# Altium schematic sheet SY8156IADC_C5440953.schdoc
size 127 x 101 mm
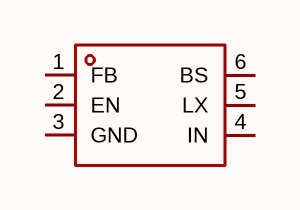
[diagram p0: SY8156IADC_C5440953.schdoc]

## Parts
U?  sy8156iadc_c5440953  [TSOT-23-6_L2.9-W1.6-P0.95-LS2.8-BL]  (value not drawn)

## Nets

Not connected (* = marked no-connect by the designer): U? 1(FB) 2(EN) 3(GND) 4(IN) 5(LX) 6(BS)

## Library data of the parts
U? = sy8156iadc_c5440953: 功能类型:降压型;工作电压:4.5V~18V;输出电压:3.3V;输出电流:6A;输出类型:固定;; Manufacturer: Silergy(矽力杰); AddInBom: yes; ModelId: 2c4039b5b88644c1bda4b4ba9e971667; ModelName: TSOT-23-6_L2.9-W1.6-H1.1-LS2.8-P0.95; ModelTransform: 110.236,114.173,0,90,0,0,0,0,0; Function: 降压型; Output Voltage: 3.3V; Output Current: 6A; Frequency - Switching: 400kHz; Synchronous Rectifier: 是; Number of Outputs: 1; Topology: 降压式; Quiescent Current: 200uA; Switch tube (built-in/external): 内置; Output Type: 固定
